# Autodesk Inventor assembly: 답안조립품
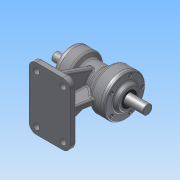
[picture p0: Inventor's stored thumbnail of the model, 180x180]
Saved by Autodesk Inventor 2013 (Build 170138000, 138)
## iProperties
Created: 2015-08
Part Number: 답안조립품
Document SubType Name: Assembly
Designer: Administrator
Author: Administrator
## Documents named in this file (10)
- C:\Users\Administrator\Desktop\450806V1027\답안조립품.iam
- C:\Users\Administrator\Desktop\450806V1027\1-본체.ipt
- C:\Users\Administrator\Desktop\450806V1027\M4x0.5.ipt
- C:\Users\Administrator\Desktop\450806V1027\뒤커버.ipt
- C:\Users\Administrator\Desktop\450806V1027\베어링 6203.ipt
- C:\Users\Administrator\Desktop\450806V1027\베어링 6205.ipt
- C:\Users\Administrator\Desktop\450806V1027\앞커버.ipt
- C:\Users\Administrator\Desktop\450806V1027\오일실 .ipt
- 오일실 .ipt
- C:\Users\Administrator\Desktop\450806V1027\축.ipt
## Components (11 placed, 2 different names)
1. 1-본체:1
2. M4x0.5:2
3. M4x0.5:3
4. M4x0.5:4
5. M4x0.5:5
6. M4x0.5:6
7. M4x0.5:1
8. M4x0.5:7
9. M4x0.5:8
10. M4x0.5:9
11. M4x0.5:10
